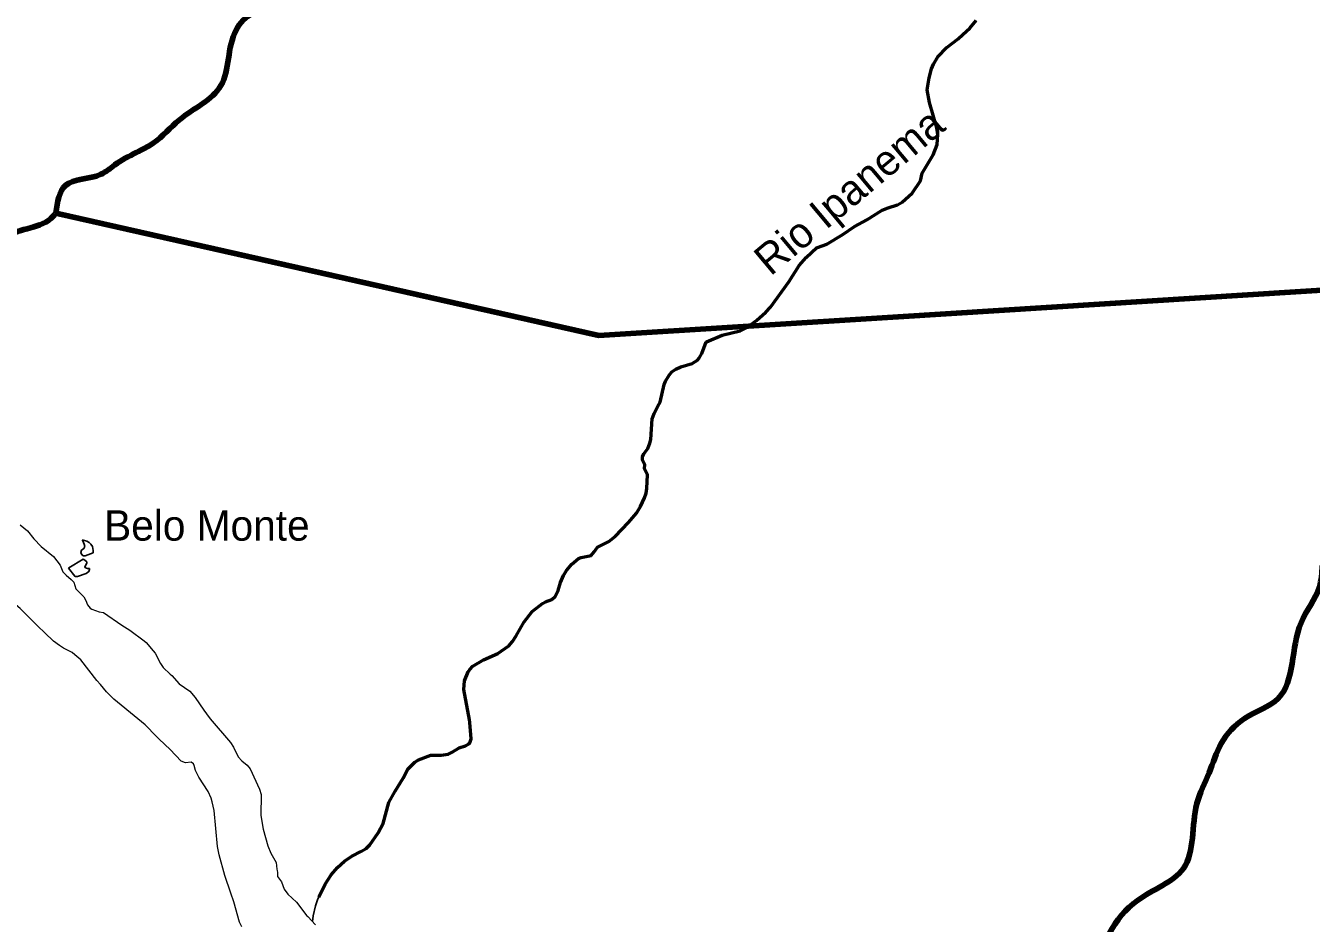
# Model space of a CAD drawing. Extents: x 553962 to 842807, y 8883888 to 9032388.
# Drawn here: x 687907 to 709060, y 8907189 to 8921950 of the extents above; entities that cross this region are included whole.
import ezdxf
from ezdxf.enums import TextEntityAlignment as Align

# ---------------------------------------------------------------- set-up
doc = ezdxf.new("R2010")
doc.units = 0
doc.header["$LTSCALE"] = 20
for name, color, linetype, lineweight in [('21', 7, 'Continuous', 25), ('24', 7, 'Continuous', 25), ('25', 7, 'Continuous', 13), ('9', 7, 'Continuous', 90)]:
    doc.layers.add(name, color=color, linetype=linetype, lineweight=lineweight)
doc.layers.add('41', color=7, linetype='Continuous')
doc.layers.add('49', color=7, linetype='Continuous')

msp = doc.modelspace()

# ---------------------------------------------------------------- linework, layer by layer
at = {"layer": '21'}
msp.add_lwpolyline([(688838.5, 8913496.28), (688910.74, 8913471.85), (688949.28, 8913452.15), (688981.44, 8913421.85), (689005.64, 8913385.59), (689018.81, 8913320.08), (689015.17, 8913282.48), (688885.64, 8913233.51), (688856.98, 8913229.24), (688829.03, 8913248.68), (688815.75, 8913288.79), (688823.04, 8913323.37), (688864.64, 8913351.6), (688880.93, 8913382.58), (688869.1, 8913424.11), (688840.15, 8913488.64)], close=True, dxfattribs=at)
for points in [[(688952.14, 8912988.54), (688957.2, 8913006.4), (688955.29, 8913022.8), (688921.86, 8913021.49), (688891.48, 8913035.11), (688877.64, 8913051.61), (688914.86, 8913110.71), (688913.29, 8913132.46), (688882.69, 8913161.53), (688854.28, 8913174.96), (688614.38, 8913034.82), (688610.31, 8913030.21)], [(688610.31, 8913030.21), (688713.39, 8912897.32), (688723.31, 8912892.53), (688740.82, 8912891.19)], [(688740.82, 8912891.19), (688757.53, 8912889.92), (688903.44, 8912939.74), (688947.93, 8912973.71), (688952.14, 8912988.54)]]:
    msp.add_lwpolyline(points, dxfattribs=at)
at = {"layer": '24', "lineweight": 53}
for points in [[(703328.72, 8921805.39), (703442.99, 8921908.08), (703548.66, 8922036.77)], [(700933.13, 8918304.14), (701087.72, 8918357.13), (701353.18, 8918514.35), (701544.98, 8918649.75), (701747.74, 8918756.08), (702001.14, 8918916.03), (702097.06, 8918956.41), (702250.92, 8919005.29), (702330.96, 8919046.84), (702493.45, 8919198.27), (702630.67, 8919399.05), (702659.58, 8919524.5), (702838.36, 8919824.34), (702905.87, 8919998.49), (702914.24, 8920160.24), (702899.98, 8920271.53), (702779.49, 8920686.84), (702738.36, 8920898.1), (702772.12, 8921093.71), (702813.31, 8921239.09), (702844.69, 8921319.07), (702917.27, 8921435.75), (703064.03, 8921594.23), (703249.34, 8921734.06), (703328.72, 8921805.39)], [(699106.03, 8916749.25), (699107.92, 8916751.85), (699364.39, 8916858.77), (699663.09, 8916929.45), (699773.95, 8916985.74), (699929.51, 8917100.88), (700086.19, 8917240.21), (700161.75, 8917318.8), (700161.75, 8917318.8), (700462.73, 8917739.72), (700633.31, 8918009.18), (700747.44, 8918138.96), (700925.23, 8918301.43), (700933.13, 8918304.14)], [(698310.3, 8915691.98), (698345.23, 8915759.09), (698414.25, 8916049.1), (698433.97, 8916103.28), (698493.16, 8916205.37), (698541, 8916255.44), (698604.47, 8916300.16), (698689.03, 8916338.56), (698872.4, 8916392.36), (698958.75, 8916447.59), (698989.04, 8916484.57), (699031.05, 8916558.43), (699106.03, 8916749.25)], [(698089.53, 8914668.19), (698092.98, 8914730.87), (698057.91, 8914805.48), (698057.73, 8914860.21), (698080.52, 8914908.16), (698146.14, 8914998.1), (698179.27, 8915082.24), (698193.24, 8915143.16), (698213.36, 8915483.85), (698249.38, 8915574.94), (698249.38, 8915574.94), (698310.3, 8915691.98)], [(697317.05, 8913373.62), (697317.92, 8913374.88), (697499.97, 8913466.08), (697607.49, 8913547.39), (697827.95, 8913780.07), (697955.32, 8913931.92), (698021, 8914043.83), (698087.15, 8914183.75), (698114.21, 8914261.74), (698128.59, 8914336.6), (698136.06, 8914565.53), (698089.33, 8914664.5), (698089.53, 8914668.19)], [(695208.72, 8910534.74), (695119.05, 8911032.82), (695125.86, 8911175.86), (695185.98, 8911322.31), (695214.96, 8911364.11), (695265.36, 8911414.88), (695441.64, 8911520.26), (695674.96, 8911623.48), (695855.79, 8911754), (695917.12, 8911825.5), (695978.81, 8911914.32), (696107.69, 8912146.41), (696241.37, 8912314.42), (696408.02, 8912448.27), (696458.17, 8912475.49), (696564.87, 8912514.11), (696620.11, 8912562.48), (696669.61, 8912662.29), (696705.83, 8912792.25), (696757.67, 8912905.97), (696806.07, 8912988.97), (696891.18, 8913095.39), (697003.99, 8913188.49), (697047.78, 8913204.08), (697212.12, 8913236.79), (697263.32, 8913295.31), (697317.05, 8913373.62)], [(692729.26, 8907617.73), (692837.01, 8907833), (692931.92, 8907984.57), (693036.83, 8908107.55), (693151.89, 8908211.51), (693272.4, 8908289.98), (693424.23, 8908367.79), (693510.75, 8908421.16), (693567.83, 8908481.12), (693707.55, 8908675.04), (693789.04, 8908827.38), (693880.7, 8909177.63), (693984.32, 8909363.29), (694118.78, 8909572.92), (694196.18, 8909725.89), (694310.54, 8909836.77), (694368.05, 8909876.06), (694574.79, 8909952.86), (694743.62, 8909954.03), (694858.1, 8909968.95), (694926.11, 8910000.53), (695042.26, 8910075.91), (695142.05, 8910109.85), (695197.58, 8910138.84), (695213.43, 8910155.14), (695235.77, 8910220.2), (695216.75, 8910490.13), (695208.72, 8910534.74)]]:
    msp.add_lwpolyline(points, dxfattribs=at)
at = {"layer": '24'}
for points in [[(703328.72, 8921805.39), (703442.99, 8921908.08), (703548.66, 8922036.77)], [(700933.13, 8918304.14), (701087.72, 8918357.13), (701353.18, 8918514.35), (701544.98, 8918649.75), (701747.74, 8918756.08), (702001.14, 8918916.03), (702097.06, 8918956.41), (702250.92, 8919005.29), (702330.96, 8919046.84), (702493.45, 8919198.27), (702630.67, 8919399.05), (702659.58, 8919524.5), (702838.36, 8919824.34), (702905.87, 8919998.49), (702914.24, 8920160.24), (702899.98, 8920271.53), (702779.49, 8920686.84), (702738.36, 8920898.1), (702772.12, 8921093.71), (702813.31, 8921239.09), (702844.69, 8921319.07), (702917.27, 8921435.75), (703064.03, 8921594.23), (703249.34, 8921734.06), (703328.72, 8921805.39)], [(699106.03, 8916749.25), (699107.92, 8916751.85), (699364.39, 8916858.77), (699663.09, 8916929.45), (699773.95, 8916985.74), (699929.51, 8917100.88), (700086.19, 8917240.21), (700161.75, 8917318.8), (700161.75, 8917318.8), (700462.73, 8917739.72), (700633.31, 8918009.18), (700747.44, 8918138.96), (700925.23, 8918301.43), (700933.13, 8918304.14)], [(698310.3, 8915691.98), (698345.23, 8915759.09), (698414.25, 8916049.1), (698433.97, 8916103.28), (698493.16, 8916205.37), (698541, 8916255.44), (698604.47, 8916300.16), (698689.03, 8916338.56), (698872.4, 8916392.36), (698958.75, 8916447.59), (698989.04, 8916484.57), (699031.05, 8916558.43), (699106.03, 8916749.25)], [(698089.53, 8914668.19), (698092.98, 8914730.87), (698057.91, 8914805.48), (698057.73, 8914860.21), (698080.52, 8914908.16), (698146.14, 8914998.1), (698179.27, 8915082.24), (698193.24, 8915143.16), (698213.36, 8915483.85), (698249.38, 8915574.94), (698249.38, 8915574.94), (698310.3, 8915691.98)], [(697317.05, 8913373.62), (697317.92, 8913374.88), (697499.97, 8913466.08), (697607.49, 8913547.39), (697827.95, 8913780.07), (697955.32, 8913931.92), (698021, 8914043.83), (698087.15, 8914183.75), (698114.21, 8914261.74), (698128.59, 8914336.6), (698136.06, 8914565.53), (698089.33, 8914664.5), (698089.53, 8914668.19)], [(695208.72, 8910534.74), (695119.05, 8911032.82), (695125.86, 8911175.86), (695185.98, 8911322.31), (695214.96, 8911364.11), (695265.36, 8911414.88), (695441.64, 8911520.26), (695674.96, 8911623.48), (695855.79, 8911754), (695917.12, 8911825.5), (695978.81, 8911914.32), (696107.69, 8912146.41), (696241.37, 8912314.42), (696408.02, 8912448.27), (696458.17, 8912475.49), (696564.87, 8912514.11), (696620.11, 8912562.48), (696669.61, 8912662.29), (696705.83, 8912792.25), (696757.67, 8912905.97), (696806.07, 8912988.97), (696891.18, 8913095.39), (697003.99, 8913188.49), (697047.78, 8913204.08), (697212.12, 8913236.79), (697263.32, 8913295.31), (697317.05, 8913373.62)], [(692627.38, 8907216.03), (692639.9, 8907309.9), (692674.32, 8907477.32), (692707.17, 8907573.54), (692837.01, 8907833), (692931.92, 8907984.57), (693036.83, 8908107.55), (693151.89, 8908211.51), (693272.4, 8908289.98), (693424.23, 8908367.79), (693510.75, 8908421.16), (693567.83, 8908481.12), (693707.55, 8908675.04), (693789.04, 8908827.38), (693880.7, 8909177.63), (693984.32, 8909363.29), (694118.78, 8909572.92), (694196.18, 8909725.89), (694310.54, 8909836.77), (694368.05, 8909876.06), (694574.79, 8909952.86), (694743.62, 8909954.03), (694858.1, 8909968.95), (694926.11, 8910000.53), (695042.26, 8910075.91), (695142.05, 8910109.85), (695197.58, 8910138.84), (695213.43, 8910155.14), (695235.77, 8910220.2), (695216.75, 8910490.13), (695208.72, 8910534.74)]]:
    msp.add_lwpolyline(points, dxfattribs=at)
at = {"layer": '25'}
for points in [[(687815.49, 8913739.43), (687934.6, 8913642.45), (688039.98, 8913510.36), (688161.99, 8913385.49), (688367.27, 8913223.01), (688472.62, 8913075.73)], [(688472.62, 8913075.73), (688515.81, 8912970.67), (688572.72, 8912913.08), (688657.82, 8912844.44), (688698.17, 8912796.31), (688734.32, 8912690.12), (688862.31, 8912558.09)], [(688008.31, 8912172.82), (687817.23, 8912367.83), (687672.61, 8912486.6)], [(688862.31, 8912558.09), (688898.17, 8912498.59), (688924.87, 8912425.18), (688966.86, 8912371.61), (688993.19, 8912354.67), (689114.55, 8912309.67), (689186.85, 8912301.89), (689186.86, 8912301.89)], [(689186.85, 8912301.89), (689489.22, 8912093.78), (689578.83, 8912037.92)], [(688219.6, 8911966.78), (688106.63, 8912072.47), (688008.31, 8912172.82)], [(689578.83, 8912037.92), (689622.71, 8912010.56), (689858.03, 8911832.06)], [(688463.76, 8911759.34), (688367.32, 8911828.6), (688219.6, 8911966.78)], [(689858.03, 8911832.06), (689891.43, 8911806.72), (690003.69, 8911671.17)], [(688717.85, 8911603.39), (688671.29, 8911641.22), (688529.42, 8911712.19), (688463.76, 8911759.34)], [(689135.47, 8911115.67), (689079.92, 8911181.43), (688815.44, 8911524.08), (688717.85, 8911603.39)], [(690003.69, 8911671.17), (690036.2, 8911631.91), (690124.28, 8911459.29), (690170.07, 8911393.11), (690282.6, 8911287.64)], [(690282.6, 8911287.64), (690310.14, 8911261.82), (690430.84, 8911126.33), (690608.84, 8911006.36), (690695.09, 8910901.92), (690838.41, 8910691.95), (690883.99, 8910634.57)], [(689754.38, 8910550.3), (689356.36, 8910876.92), (689236.61, 8910995.92), (689135.47, 8911115.67)], [(690105.84, 8910215.61), (690059.92, 8910258.16), (689871.02, 8910454.59), (689754.38, 8910550.3)], [(690883.99, 8910634.57), (690943.91, 8910550.7), (691277.7, 8910162.7), (691329, 8910084.34), (691401.22, 8909927.09), (691461.89, 8909862.37), (691549.55, 8909789.55), (691600.11, 8909727.45), (691754.69, 8909393.06), (691782.01, 8909306.65), (691774.24, 8908959.57), (691815.3, 8908738.39), (691889.9, 8908460.67), (691940.95, 8908340.71), (692026.27, 8908188.89), (692038.93, 8908078.59), (692044.79, 8908056.69)], [(690973.82, 8909186.54), (690959.39, 8909246.92), (690907.64, 8909357.32), (690755.79, 8909591.01), (690701.86, 8909701.67), (690681.35, 8909786.18), (690666.42, 8909810.26), (690629.51, 8909837.86), (690534.67, 8909826.16), (690465.15, 8909853.33), (690285.02, 8910049.59), (690105.84, 8910215.61)], [(691088.54, 8908313.88), (691062.83, 8908449.14), (691008.38, 8909041.88), (690973.82, 8909186.54)], [(691281.37, 8907685.43), (691182.39, 8907975.49), (691088.54, 8908313.88)], [(692044.79, 8908056.69), (692052.82, 8908026.72), (692050.71, 8907961.01), (692118.3, 8907868.3), (692160.07, 8907748.41), (692220.32, 8907669.35), (692364.92, 8907535.6), (692534.05, 8907312.77), (692551.49, 8907299.65), (692676.39, 8907162.12)], [(691462.26, 8907129.93), (691426.99, 8907208.97), (691331.21, 8907539.37), (691281.37, 8907685.43)]]:
    msp.add_lwpolyline(points, dxfattribs=at)
at = {"layer": '9'}
msp.add_line((702263.18, 8917164.23), (717332.23, 8918103.28), dxfattribs=at)
msp.add_lwpolyline([(688404.93, 8918868.12), (697336.49, 8916857.21), (702263.18, 8917164.23)], dxfattribs=at)
for points in [[(688404.93, 8918868.12), (688561.44, 8919324.38), (689144.73, 8919505.96), (689372.57, 8919659.58), (689727.14, 8919864.78), (690005.78, 8920018.78), (690435.68, 8920401.8), (691118.68, 8920963.94), (691368.16, 8921877.38), (691646.17, 8922157.99), (692203.94, 8922364.7), (692354.7, 8922695), (691945.06, 8923350.34), (691967.96, 8923856.95), (691992.73, 8923983.74), (691990.85, 8924363.56), (691810.43, 8924893.98), (691605.74, 8925196.33), (690588.79, 8925391.37), (690130.86, 8925539.91), (689951.82, 8925791.8), (690098.58, 8926932.38), (689816.94, 8927386.09), (689611.87, 8927764.4), (689634.64, 8928296.34), (689708.33, 8928803.32), (689427.82, 8929029.14), (689071.11, 8929254.4), (688969.39, 8929278.97)], [(685563.35, 8914000.08), (685411.91, 8914185.99), (685156.8, 8914412), (685077.72, 8914993.82), (685249.87, 8916134.59), (685677.52, 8916973.38), (686082.14, 8917330.89), (686664.68, 8917664.39), (687019.14, 8917894.92), (687575.02, 8918481.44), (688360.75, 8918816.45), (688404.93, 8918868.12)], [(705207.93, 8903769.64), (705180.68, 8904747.44), (705463.83, 8906360.03), (706198.67, 8907564.56), (706955.49, 8908091.1), (707178.81, 8909156.28), (707379.5, 8909664.2), (707580.31, 8910146.81), (707959.28, 8910554.77), (708516.42, 8910888.09), (708891.26, 8912131.65), (709193.17, 8912716.29), (709242.21, 8913071.16)]]:
    msp.add_spline(points, degree=3, dxfattribs=at)

# ---------------------------------------------------------------- texts
at = {"layer": '41'}
msp.add_text('Belo Monte', height=500, dxfattribs=at).set_placement((689197.47, 8913481.5))
at = {"layer": '49'}
msp.add_text('Rio Ipanema', height=500, rotation=39.92, dxfattribs=at).set_placement((701615.27, 8919036.73), align=Align.CENTER)

doc.saveas('drawing.dxf')
